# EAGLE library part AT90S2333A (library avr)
MICROCONTROLLER 2 Kbytes FLASH 128 bytes SRAM 128 bytes EEPROM UART 6-channel 10-bit ADC
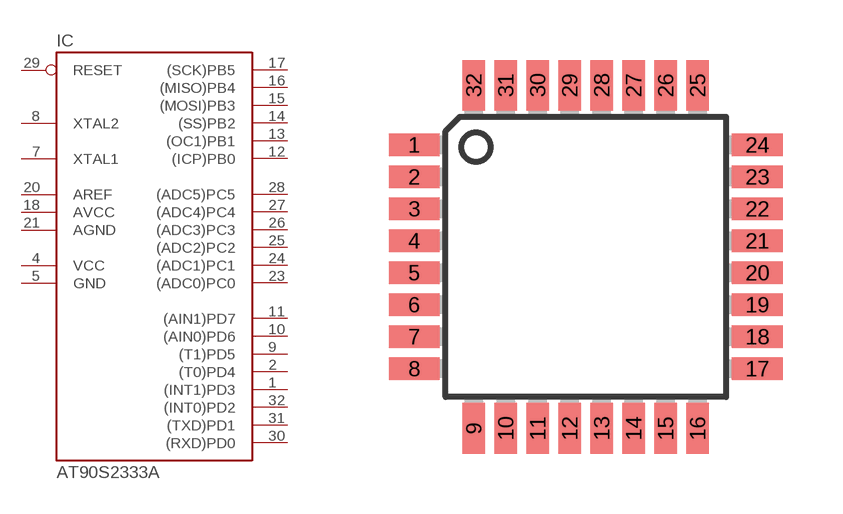
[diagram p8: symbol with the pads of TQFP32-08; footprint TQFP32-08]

Designator prefix IC

## AT90S2333AA  [TQFP32-08]
1  (INT1)PD3
2  (T0)PD4
3  NC1  nc
4  VCC  pwr
5  GND  pwr
6  NC2  nc
7  XTAL1
8  XTAL2
9  (T1)PD5
10  (AIN0)PD6
11  (AIN1)PD7
12  (ICP)PB0
13  (OC1)PB1
14  (SS)PB2
15  (MOSI)PB3
16  (MISO)PB4
17  (SCK)PB5
18  AVCC  pwr
19  NC3  nc
20  AREF  pwr
21  AGND  pwr
22  NC4  nc
23  (ADC0)PC0
24  (ADC1)PC1
25  (ADC2)PC2
26  (ADC3)PC3
27  (ADC4)PC4
28  (ADC5)PC5
29  RESET  in
30  (RXD)PD0
31  (TXD)PD1
32  (INT0)PD2

## Footprint TQFP32-08 (pad centres in mm)
Thin Plasic Quad Flat Package Grid 0.8 mm
smd 1.27 x 0.559: 1 -4.293,2.8; 2 -4.293,2; 3 -4.293,1.2; 4 -4.293,0.4; 5 -4.293,-0.4; 6 -4.293,-1.2; 7 -4.293,-2; 8 -4.293,-2.8; 17 4.293,-2.8; 18 4.293,-2; 19 4.293,-1.2; 20 4.293,-0.4; 21 4.293,0.4; 22 4.293,1.2; 23 4.293,2; 24 4.293,2.8
smd 0.559 x 1.27: 9 -2.8,-4.293; 10 -2,-4.293; 11 -1.2,-4.293; 12 -0.4,-4.293; 13 0.4,-4.293; 14 1.2,-4.293; 15 2,-4.293; 16 2.8,-4.293; 25 2.8,4.293; 26 2,4.293; 27 1.2,4.293; 28 0.4,4.293; 29 -0.4,4.293; 30 -1.2,4.293; 31 -2,4.293; 32 -2.8,4.293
